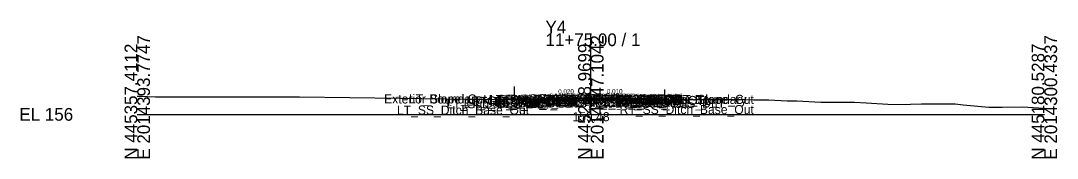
# Model space of a CAD drawing. Extents: x -26 to 203, y -10 to 4021.
# Drawn here: x -25.7 to 202.8, y 3490.3 to 3520.7 of the extents above; entities that cross this region are included whole.
import ezdxf

# ---------------------------------------------------------------- set-up
doc = ezdxf.new("R2010")
doc.units = 0
for name, color, linetype in [('Default', 7, 'Continuous'), ('Exist CMT Pavement', 7, 'Continuous'), ('Exist Cross Section Cell', 7, 'Continuous'), ('Exist XS Center Line Elevation Label', 7, 'Continuous'), ('Exist XS Ground Line', 7, 'Continuous'), ('Prop CMT Pvmt Course 1', 7, 'Continuous'), ('Prop CMT Pvmt Course 1 Wedge', 7, 'Continuous'), ('Prop CMT Pvmt Course 2', 7, 'Continuous'), ('Prop CMT Pvmt Course 2 Wedge', 7, 'Continuous'), ('Prop CMT Pvmt Course 3', 7, 'Continuous'), ('Prop CMT Pvmt Course 3 Wedge', 7, 'Continuous'), ('Prop CMT Pvmt Surface', 7, 'Continuous'), ('Prop CMT Pvmt Surface Shoulder', 7, 'Continuous'), ('Prop CMT Pvmt Wedge Surface 1', 7, 'Continuous'), ('Prop CMT Pvmt Wedge Surface 2', 7, 'Continuous'), ('Prop CMT Pvmt Wedge Surface 3', 7, 'Continuous'), ('Prop CMT Shld Paved Course 1', 7, 'Continuous'), ('Prop CMT Shld Paved Course 2', 7, 'Continuous'), ('Prop CMT Shld Paved Course 3', 7, 'Continuous'), ('Prop CMT Slope Grass', 7, 'Continuous'), ('Prop CMT Subgrade Earthwork', 7, 'Continuous'), ('Prop XS Earthwork Shape', 7, 'Continuous'), ('Prop XS SE Text', 7, 'Continuous'), ('Prop XS Wedging', 7, 'Continuous'), ('Scratch_Level_0', 7, 'Continuous'), ('Scratch_Level_1', 7, 'Continuous')]:
    doc.layers.add(name, color=color, linetype=linetype)

msp = doc.modelspace()

# ---------------------------------------------------------------- linework, layer by layer
at = {"layer": 'Exist CMT Pavement'}
for points in [[(90.17, 3503.29), (99.76, 3503.49)], [(99.76, 3503.49), (109.33, 3503.28)]]:
    msp.add_lwpolyline(points, dxfattribs=at)
at = {"layer": 'Exist Cross Section Cell'}
for p, q in [((100, 3500), (100, 3517.86)), ((0, 3500), (100, 3500)), ((100, 3500), (200, 3500))]:
    msp.add_line(p, q, dxfattribs=at)
at = {"layer": 'Exist XS Ground Line'}
msp.add_lwpolyline([(0, 3504.01), (0.52, 3504), (4.04, 3503.88), (4.48, 3503.88), (26.82, 3503.86), (32.86, 3503.9), (33.9, 3503.89), (35.74, 3503.88), (57.98, 3503.55), (62.77, 3503.47), (79.01, 3503.31), (82.87, 3503.32), (85.85, 3503.31), (88.07, 3503.24), (98.46, 3503.46), (98.77, 3503.47), (99.76, 3503.49), (110.33, 3503.26), (112.55, 3503.31), (116.86, 3503.26), (118.06, 3503.23), (122.83, 3503.31), (128.43, 3503.3), (134.13, 3503.31), (135.9, 3503.24), (139.25, 3503.18), (143.3, 3503.01), (145.44, 3502.96), (150.7, 3502.71), (156.75, 3502.68), (158.11, 3502.67), (160.67, 3502.53), (165.51, 3502.26), (168.06, 3502.16), (172.91, 3502.33), (179.37, 3502.35), (180.31, 3502.29), (182.1, 3502.13), (187.72, 3501.6), (190.68, 3501.6), (195.12, 3501.63), (200, 3501.38)], dxfattribs=at)
at = {"layer": 'Prop CMT Pvmt Course 1'}
for points in [[(100, 3503.65), (89.17, 3503.43)], [(89.17, 3503.43), (89.17, 3503.18)], [(90.17, 3503.33), (100, 3503.53)], [(100, 3503.4), (100, 3503.65)], [(100, 3503.65), (110.33, 3503.55)], [(100, 3503.4), (100, 3503.65)], [(100, 3503.53), (100, 3503.4), (100, 3503.4)], [(109.33, 3503.43), (100, 3503.53)], [(100, 3503.53), (100, 3503.4), (100, 3503.4)], [(109.33, 3503.31), (109.33, 3503.43)], [(110.33, 3503.55), (110.33, 3503.3)], [(89.17, 3503.18), (90.17, 3503.2)], [(90.17, 3503.2), (90.17, 3503.33)], [(110.33, 3503.3), (109.33, 3503.31)]]:
    msp.add_lwpolyline(points, dxfattribs=at)
at = {"layer": 'Prop CMT Pvmt Course 1 Wedge'}
for points in [[(100, 3503.53), (90.17, 3503.33)], [(100, 3503.53), (109.33, 3503.43)]]:
    msp.add_lwpolyline(points, dxfattribs=at)
at = {"layer": 'Prop CMT Pvmt Course 2'}
for points in [[(90.17, 3503.2), (89.17, 3503.18)], [(89.17, 3503.18), (89.17, 3502.85)], [(89.17, 3502.85), (90.17, 3502.87)], [(90.17, 3502.87), (90.17, 3503.2)], [(109.33, 3502.97), (109.33, 3503.31)], [(109.33, 3503.31), (110.33, 3503.3)], [(110.33, 3502.96), (109.33, 3502.97)], [(110.33, 3503.3), (110.33, 3502.96)]]:
    msp.add_lwpolyline(points, dxfattribs=at)
at = {"layer": 'Prop CMT Pvmt Course 2 Wedge'}
for points in [[(100, 3503.4), (90.17, 3503.2)], [(100, 3503.4), (109.33, 3503.31)]]:
    msp.add_lwpolyline(points, dxfattribs=at)
at = {"layer": 'Prop CMT Pvmt Course 3'}
for points in [[(90.17, 3502.87), (89.17, 3502.85)], [(89.17, 3502.85), (89.17, 3502.52)], [(89.17, 3502.52), (90.17, 3502.54)], [(90.17, 3502.54), (90.17, 3502.87)], [(109.33, 3502.97), (110.33, 3502.96)], [(109.33, 3502.64), (109.33, 3502.97)], [(110.33, 3502.63), (109.33, 3502.64)], [(110.33, 3502.96), (110.33, 3502.63)]]:
    msp.add_lwpolyline(points, dxfattribs=at)
at = {"layer": 'Prop CMT Pvmt Course 3 Wedge'}
for points in [[(100, 3503.07), (90.17, 3502.87)], [(100, 3503.07), (109.33, 3502.97)]]:
    msp.add_lwpolyline(points, dxfattribs=at)
at = {"layer": 'Prop CMT Pvmt Surface'}
for points in [[(100, 3503.65), (89.17, 3503.43)], [(100, 3503.65), (110.33, 3503.55)]]:
    msp.add_lwpolyline(points, dxfattribs=at)
at = {"layer": 'Prop CMT Pvmt Surface Shoulder'}
for points in [[(89.17, 3503.43), (89.17, 3503.43)], [(110.33, 3503.55), (110.33, 3503.55)]]:
    msp.add_lwpolyline(points, dxfattribs=at)
at = {"layer": 'Prop CMT Pvmt Wedge Surface 1'}
for points in [[(89.17, 3503.18), (89.17, 3503.43)], [(100, 3503.53), (90.17, 3503.33)], [(100, 3503.53), (109.33, 3503.43)], [(109.33, 3503.43), (109.33, 3503.31)], [(110.33, 3503.3), (110.33, 3503.55)], [(90.17, 3503.2), (89.17, 3503.18)], [(90.17, 3503.33), (90.17, 3503.2)], [(109.33, 3503.31), (110.33, 3503.3)]]:
    msp.add_lwpolyline(points, dxfattribs=at)
at = {"layer": 'Prop CMT Pvmt Wedge Surface 2'}
for points in [[(89.17, 3503.18), (89.17, 3503.43)], [(110.33, 3503.3), (110.33, 3503.55)], [(100, 3503.4), (89.17, 3503.18)], [(100, 3503.4), (110.33, 3503.3)]]:
    msp.add_lwpolyline(points, dxfattribs=at)
at = {"layer": 'Prop CMT Pvmt Wedge Surface 3'}
for points in [[(89.17, 3502.85), (89.17, 3503.43)], [(110.33, 3502.96), (110.33, 3503.55)], [(100, 3503.07), (89.17, 3502.85)], [(100, 3503.07), (110.33, 3502.96)]]:
    msp.add_lwpolyline(points, dxfattribs=at)
at = {"layer": 'Prop CMT Shld Paved Course 1'}
for points in [[(89.17, 3503.43), (88.92, 3503.18)], [(89.17, 3503.43), (89.17, 3503.43)], [(89.17, 3503.18), (89.17, 3503.43)], [(110.33, 3503.55), (110.33, 3503.55)], [(110.33, 3503.55), (110.58, 3503.29)], [(110.33, 3503.3), (110.33, 3503.55)], [(88.92, 3503.18), (89.17, 3503.18)], [(110.58, 3503.29), (110.33, 3503.3)]]:
    msp.add_lwpolyline(points, dxfattribs=at)
at = {"layer": 'Prop CMT Shld Paved Course 2'}
for points in [[(89.17, 3503.18), (88.92, 3503.18), (88.58, 3502.84)], [(88.58, 3502.84), (89.17, 3502.85)], [(89.17, 3502.85), (89.17, 3503.18)], [(110.33, 3503.3), (110.58, 3503.29), (110.93, 3502.95)], [(110.33, 3502.96), (110.33, 3503.3)], [(110.93, 3502.95), (110.33, 3502.96)]]:
    msp.add_lwpolyline(points, dxfattribs=at)
at = {"layer": 'Prop CMT Shld Paved Course 3'}
for points in [[(87.74, 3502.49), (89.17, 3502.52)], [(89.17, 3502.85), (88.58, 3502.84), (88.24, 3502.5)], [(89.17, 3502.52), (89.17, 3502.85)], [(110.33, 3502.63), (110.33, 3502.96)], [(110.33, 3502.96), (110.93, 3502.95), (111.27, 3502.61)], [(111.77, 3502.6), (110.33, 3502.63)]]:
    msp.add_lwpolyline(points, dxfattribs=at)
at = {"layer": 'Prop CMT Slope Grass'}
for points in [[(89.17, 3503.43), (83.17, 3503.32)], [(110.33, 3503.55), (116.33, 3503.26)]]:
    msp.add_lwpolyline(points, dxfattribs=at)
at = {"layer": 'Prop CMT Subgrade Earthwork'}
for points in [[(87.74, 3502.49), (83.17, 3503.32)], [(89.17, 3502.52), (87.74, 3502.49)], [(90.17, 3502.54), (89.17, 3502.52)], [(90.17, 3502.54), (90.17, 3503.29)], [(109.33, 3502.64), (109.33, 3503.28)], [(109.33, 3502.64), (110.33, 3502.63)], [(110.33, 3502.63), (111.77, 3502.6)], [(111.77, 3502.6), (116.33, 3503.26)]]:
    msp.add_lwpolyline(points, dxfattribs=at)
at = {"layer": 'Prop XS Earthwork Shape'}
for points in [[(98.77, 3503.47), (99.76, 3503.49), (98.46, 3503.46)], [(83.17, 3503.32), (87.74, 3502.49), (90.17, 3502.54), (90.17, 3503.29), (88.07, 3503.24), (85.85, 3503.31)], [(109.33, 3503.28), (109.33, 3502.64), (111.77, 3502.6), (116.33, 3503.26), (112.55, 3503.31), (110.33, 3503.26)]]:
    msp.add_lwpolyline(points, close=True, dxfattribs=at)
at = {"layer": 'Prop XS Wedging'}
for p, q in [((100, 3503.53), (90.17, 3503.33)), ((99.76, 3503.49), (100, 3503.48)), ((109.33, 3503.43), (100, 3503.53)), ((100, 3503.53), (100, 3503.48)), ((100, 3503.48), (100, 3503.53)), ((100, 3503.48), (106.94, 3503.33)), ((109.33, 3503.31), (109.33, 3503.43)), ((90.17, 3503.33), (90.17, 3503.29)), ((106.94, 3503.33), (109.33, 3503.31))]:
    msp.add_line(p, q, dxfattribs=at)
for points in [[(90.17, 3503.29), (98.46, 3503.46), (98.77, 3503.47), (99.76, 3503.49)], [(90.17, 3503.29), (90.17, 3503.29)]]:
    msp.add_lwpolyline(points, dxfattribs=at)
at = {"layer": 'Scratch_Level_1'}
for p, q in [((83.17, 3502.95), (83.17, 3506.15)), ((116.33, 3503.07), (116.33, 3505.5))]:
    msp.add_line(p, q, dxfattribs=at)

# ---------------------------------------------------------------- texts
at = {"layer": 'Default'}
msp.add_text('-', height=0.0001, dxfattribs=at).set_placement((0, 3500))
at = {"layer": 'Exist Cross Section Cell'}
for s, p in [('Y4', (90, 3517.86)), ('11+75.00 / 1', (90, 3515.06)), ('EL 156', (-26, 3498.6))]:
    msp.add_text(s, height=2.8, dxfattribs=at).set_placement(p)
for s, p in [('E 2014393.7747', (2.8, 3490)), ('E 2014347.1042', (102.8, 3490)), ('E 2014300.4337', (202.8, 3490)), ('N 445357.4112', (0, 3490)), ('N 445268.9699', (100, 3490)), ('N 445180.5287', (200, 3490))]:
    msp.add_text(s, height=2.8, rotation=90, dxfattribs=at).set_placement(p)
at = {"layer": 'Exist XS Center Line Elevation Label'}
msp.add_text('159.48', height=2, dxfattribs=at).set_placement((95.96, 3498.48))
at = {"layer": 'Prop XS SE Text'}
for s, rotation, p in [('0.020', 1.1458, (92.82, 3504.51)), ('0.010', 359.4271, (103.54, 3504.61))]:
    msp.add_text(s, height=1, rotation=rotation, dxfattribs=at).set_placement(p)
at = {"layer": 'Scratch_Level_0'}
for s, p in [('Exterior Boundary', (54.42, 3502.4)), ('LT_Slope_Cut', (59.92, 3502.4)), ('LT_Sub_OSS_DLT', (68.15, 3501.35)), ('LT_Sub_Trench_Out', (71.94, 3501.49)), ('LT_GS_OS_CTL', (72.54, 3501.95)), ('LT_PS3_Shelf_Out', (74.06, 3501.83)), ('LT_Sub Tie Out', (77.51, 3502.29)), ('LT_PV_OEEOP_EG', (77.72, 3502.29)), ('LT_PS3_OEOP', (78.81, 3501.84)), ('LT_PS2_OEOP', (79.15, 3502.18)), ('LT_Sub_OEOT', (79.25, 3501.52)), ('LT_PV2_OEOT', (79.35, 3502.18)), ('LT_PV3_OEOT', (79.35, 3501.85)), ('LT_Sub_OEEOP', (79.38, 3501.54)), ('LT_PV2_OEEOP', (79.48, 3502.2)), ('LT_PV3_OEEOP', (79.48, 3501.87)), ('LT_PV1_OEOT', (79.91, 3502.43)), ('LT_PS1_OEOP', (79.98, 3502.43)), ('LT_PV1_OEEOP', (80.05, 3502.33)), ('RT_PV_IEEOP_EG', (88.14, 3502.48)), ('LT_PV_IEEOP_EG', (88.19, 3502.48)), ('RT_PV2_IEEOP', (89.91, 3502.4)), ('RT_PV3_IEEOP', (89.91, 3502.07)), ('LT_PV2_IEEOP', (89.95, 3502.4)), ('LT_PV3_IEEOP', (89.95, 3502.07)), ('RT_PV1_IEEOP', (90.47, 3502.53)), ('LT_PV1_IEEOP', (90.52, 3502.53)), ('PV2_PGL', (93.91, 3502.4)), ('PV1_PGL', (94.47, 3502.65)), ('RT_Sub_Trench_Out', (95.92, 3501.6)), ('RT_Sub Tie Out', (96.62, 3502.28)), ('RT_PV_OEEOP_EG', (96.82, 3502.28)), ('RT_PS3_Shelf_Out', (97.36, 3501.94)), ('RT_Sub_OEEOP', (98.5, 3501.64)), ('RT_PV2_OEEOP', (98.59, 3502.31)), ('RT_PV3_OEEOP', (98.59, 3501.97)), ('RT_PV1_OEEOP', (99.16, 3502.43)), ('RT_Sub_OEOT', (100.36, 3501.63)), ('RT_PV2_OEOT', (100.46, 3502.3)), ('RT_PV3_OEOT', (100.46, 3501.96)), ('RT_PS2_OEOP', (100.77, 3502.29)), ('RT_PV1_OEOT', (101.02, 3502.55)), ('RT_PS1_OEOP', (101.09, 3502.55)), ('RT_PS3_OEOP', (101.11, 3501.95)), ('RT_GS_OS_CTL', (105.65, 3502.07)), ('RT_Sub_OSS_DLT', (106.1, 3501.46)), ('Exterior Boundary', (112.95, 3502.3)), ('RT_Slope_Cut', (118.4, 3502.3)), ('LT_SS_Ditch_Base_Out', (57.25, 3499.95)), ('RT_SS_Ditch_Base_Out', (106.36, 3500.07))]:
    msp.add_text(s, height=2, dxfattribs=at).set_placement(p)

doc.saveas('drawing.dxf')
